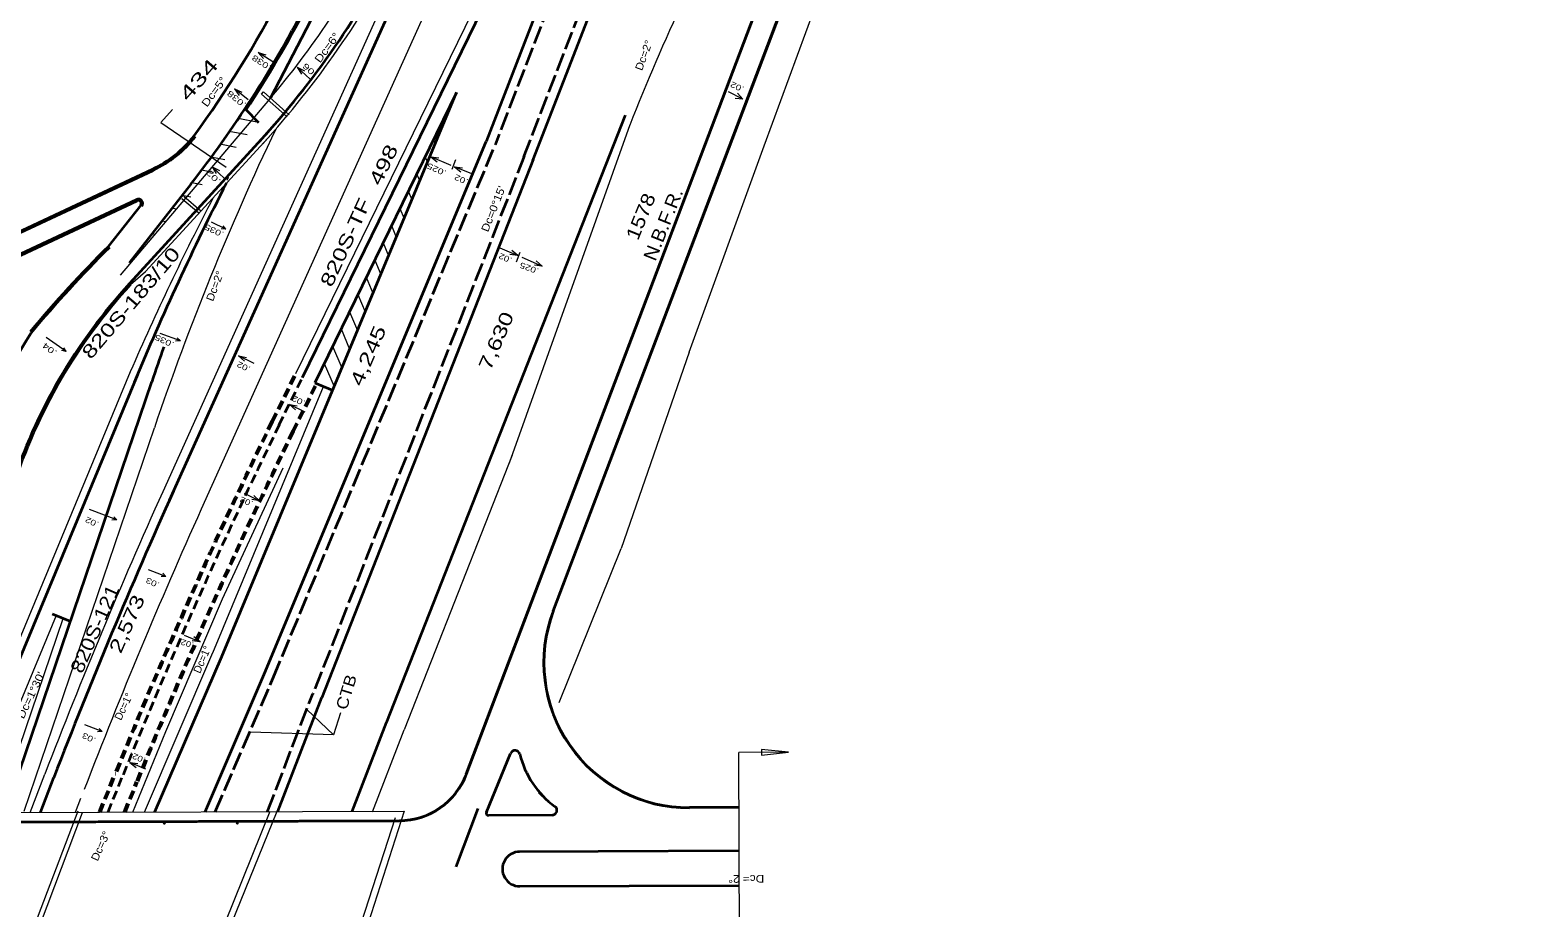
# Model space of a CAD drawing. Extents: x 2354993 to 2372084, y 6966390 to 6990057.
# Drawn here: x 2364884 to 2366452, y 6980481 to 6981393 of the extents above; entities that cross this region are included whole.
import ezdxf

# ---------------------------------------------------------------- set-up
doc = ezdxf.new("R2010")
doc.units = 0
doc.header["$LTSCALE"] = 3.2
doc.header["$PDMODE"] = 32
doc.header["$PDSIZE"] = 1.6
doc.linetypes.add('LONG_DASHED', pattern=[7.5, 6, -1.5])
doc.linetypes.add('MEDIUM_DASHED', pattern=[4.5, 3, -1.5])
for name, color, linetype, lineweight in [('1', 7, 'Continuous', 13), ('11', 7, 'Continuous', 13), ('12', 7, 'Continuous', 13), ('13', 7, 'Continuous', 13), ('15', 7, 'Continuous', 13), ('17', 7, 'Continuous', 13), ('19', 7, 'Continuous', 13), ('2', 7, 'Continuous', 35), ('4', 7, 'Continuous', 13), ('5', 7, 'Continuous', 35), ('7', 7, 'Continuous', 13), ('9', 7, 'Continuous', 13)]:
    doc.layers.add(name, color=color, linetype=linetype, lineweight=lineweight)

msp = doc.modelspace()

# ---------------------------------------------------------------- linework, layer by layer
at = {"layer": '1'}
for p, q in [((2365090.897, 6981239.272), (2365087.397, 6981239.272)), ((2365089.147, 6981241.022), (2365089.147, 6981237.522)), ((2365087.853, 6981186.245), (2365072.864, 6981193.81)), ((2365087.853, 6981186.245), (2365082.859, 6981186.653)), ((2365087.853, 6981186.245), (2365084.997, 6981189.742)), ((2364921.894, 6981059.311), (2364901.059, 6981073.892)), ((2365040.609, 6981070.164), (2365019.682, 6981078.089)), ((2365040.609, 6981070.164), (2365037.401, 6981073.341)), ((2364921.894, 6981059.311), (2364917.006, 6981060.413)), ((2364921.894, 6981059.311), (2364919.555, 6981063.172)), ((2365040.609, 6981070.164), (2365035.6, 6981070.044)), ((2364974.461, 6980884.074), (2364946.096, 6980894.816)), ((2364974.461, 6980884.074), (2364971.253, 6980887.251)), ((2364974.461, 6980884.074), (2364969.452, 6980883.954)), ((2365025.65, 6980825.433), (2365007.554, 6980832.286)), ((2365025.65, 6980825.433), (2365020.641, 6980825.313)), ((2365025.65, 6980825.433), (2365022.442, 6980828.61)), ((2364959.397, 6980664.047), (2364941.301, 6980670.9)), ((2364959.397, 6980664.047), (2364956.189, 6980667.224)), ((2364959.397, 6980664.047), (2364954.388, 6980663.927))]:
    msp.add_line(p, q, dxfattribs=at)
at = {"layer": '11'}
for q in [(2365610.405, 6981329.056), (2365619.803, 6981327.948), (2365617.401, 6981322.432)]:
    msp.add_line((2365625.59, 6981321.562), q, dxfattribs=at)
msp.add_lwpolyline([(2365417.107, 6980596.157), (2365413.024, 6980600.471), (2365417.107, 6980596.157)], dxfattribs=at)
at = {"layer": '12'}
for p, q in [((2365125.058, 6981326.907), (2365127.058, 6981329.143)), ((2365125.058, 6981326.907), (2365151.575, 6981303.182)), ((2365127.058, 6981329.143), (2365153.598, 6981305.398)), ((2365059.879, 6981202.904), (2365042.143, 6981217.955)), ((2365061.904, 6981205.119), (2365044.105, 6981220.225)), ((2364889.34, 6980463.063), (2364934.323, 6980581.712)), ((2364895.069, 6980464.071), (2364938.998, 6980579.939)), ((2365133.691, 6980580.838), (2365086.673, 6980464.691)), ((2365140.767, 6980580.861), (2365093.748, 6980464.714)), ((2365263.831, 6980574.448), (2365228.608, 6980465.09)), ((2365273.39, 6980581.292), (2365235.902, 6980464.902))]:
    msp.add_line(p, q, dxfattribs=at)
at = {"layer": '13'}
msp.add_lwpolyline([(2365032.472, 6981310.938), (2365020.251, 6981297.462), (2365088.313, 6981250.891)], dxfattribs=at)
at = {"layer": '15'}
for p in [(2365672.832, 6980642.571), (2365622.178, 6980409.332)]:
    msp.add_line(p, (2365621.422, 6980642.404), dxfattribs=at)
msp.add_lwpolyline([(2365672.832, 6980642.571), (2365644.822, 6980645.48), (2365644.842, 6980639.481)], close=True, dxfattribs=at)
at = {"layer": '19'}
for p, q in [((2365121.444, 6981370.154), (2365126.945, 6981363.93)), ((2365121.444, 6981370.154), (2365129.403, 6981367.761)), ((2365136.609, 6981360.443), (2365121.444, 6981370.154)), ((2365162.209, 6981354.708), (2365166.546, 6981347.624)), ((2365162.209, 6981354.708), (2365169.632, 6981350.969)), ((2365175.457, 6981342.512), (2365162.209, 6981354.708)), ((2365097.007, 6981332.243), (2365101.772, 6981325.439)), ((2365097.007, 6981332.243), (2365104.646, 6981328.969)), ((2365110.982, 6981320.886), (2365097.007, 6981332.243)), ((2365301.151, 6981261.455), (2365307.649, 6981256.281)), ((2365301.151, 6981261.455), (2365309.405, 6981260.48)), ((2365322.242, 6981252.661), (2365301.151, 6981261.455)), ((2365073.768, 6981251.325), (2365077.965, 6981244.157)), ((2365073.768, 6981251.325), (2365081.116, 6981247.442)), ((2365086.775, 6981238.871), (2365073.768, 6981251.325)), ((2365326.815, 6981258.432), (2365322.862, 6981248.333)), ((2365325.805, 6981251.294), (2365332.303, 6981246.12)), ((2365325.805, 6981251.294), (2365334.058, 6981250.319)), ((2365343.62, 6981243.866), (2365325.805, 6981251.294)), ((2365101.134, 6981054.568), (2365107.331, 6981049.037)), ((2365101.134, 6981054.568), (2365109.32, 6981053.131)), ((2365117.339, 6981046.715), (2365101.134, 6981054.568)), ((2365153.99, 6981004.019), (2365160.187, 6980998.488)), ((2365153.99, 6981004.019), (2365162.176, 6981002.582)), ((2365170.195, 6980996.166), (2365153.99, 6981004.019)), ((2365122.978, 6980903.802), (2365114.831, 6980905.444)), ((2365061.108, 6980757.5), (2365052.846, 6980758.396)), ((2364988.033, 6980631.938), (2364996.28, 6980630.907))]:
    msp.add_line(p, q, dxfattribs=at)
for points in [[(2365106.977, 6980912.062), (2365122.978, 6980903.802), (2365116.923, 6980909.487)], [(2365044.423, 6980764.273), (2365061.108, 6980757.5), (2365054.562, 6980762.612)], [(2365004.606, 6980624.894), (2364988.033, 6980631.938), (2364994.495, 6980626.72)]]:
    msp.add_lwpolyline(points, dxfattribs=at)
at = {"layer": '2'}
for p, q in [((2365683.228, 6982117.169), (2365358.55, 6981277.634)), ((2365407.217, 6981257.934), (2365731.885, 6982097.447)), ((2365029.335, 6980904.779), (2365448.587, 6981835.455)), ((2365382.326, 6981472.187), (2365167.295, 6981031.876)), ((2365083.539, 6980742.181), (2365327.767, 6981328.565)), ((2365327.767, 6981328.565), (2365180.29, 6981026.581)), ((2365132.253, 6981287.979), (2364987.673, 6981129.869)), ((2365127.849, 6980723.726), (2365358.55, 6981277.634)), ((2365407.521, 6981258.707), (2365187.636, 6980699.526)), ((2365051.37, 6981233.14), (2364987.232, 6981151.398)), ((2364999.333, 6981211.369), (2364965.597, 6981168.373)), ((2364987.673, 6981129.869), (2364988.78, 6981128.857)), ((2364995.931, 6981035.023), (2364806.866, 6980579.777)), ((2364861.207, 6980586.955), (2365010.841, 6981027.825)), ((2365180.29, 6981026.581), (2365198.806, 6981019.036)), ((2364926.249, 6980778.591), (2364907.779, 6980786.263)), ((2365014.176, 6980580.45), (2365083.539, 6980742.181)), ((2365066.472, 6980580.62), (2365127.849, 6980723.726)), ((2365141.795, 6980580.864), (2365187.636, 6980699.526)), ((2364766.428, 6980569.647), (2365268.294, 6980571.275))]:
    msp.add_line(p, q, dxfattribs=at)
at = {"layer": '2', "linetype": 'LONG_DASHED'}
for p, q in [((2365692.555, 6982113.562), (2365367.877, 6981274.027)), ((2365397.89, 6981261.541), (2365722.558, 6982101.054)), ((2365137.08, 6980719.881), (2365367.781, 6981273.789)), ((2365398.215, 6981262.367), (2365178.33, 6980703.186)), ((2365076.877, 6980580.654), (2365137.08, 6980719.881)), ((2365131.062, 6980580.83), (2365178.308, 6980703.13))]:
    msp.add_line(p, q, dxfattribs=at)
at = {"layer": '2', "lineweight": 13}
for p, q in [((2365372.833, 6981167.08), (2365391.564, 6981159.03)), ((2365391.564, 6981159.03), (2365383.322, 6981160.095)), ((2365391.564, 6981159.03), (2365385.123, 6981164.274)), ((2365390.132, 6981152.333), (2365393.897, 6981162.504)), ((2365395.606, 6981157.245), (2365416.941, 6981148.076)), ((2365416.941, 6981148.076), (2365410.499, 6981153.32)), ((2365416.941, 6981148.076), (2365408.698, 6981149.141)), ((2365199.84, 6980660.583), (2365172.164, 6980687.071)), ((2365206.926, 6980683.485), (2365199.84, 6980660.583)), ((2365199.84, 6980660.583), (2365113.429, 6980663.421))]:
    msp.add_line(p, q, dxfattribs=at)
at = {"layer": '2', "linetype": 'MEDIUM_DASHED'}
for p, q in [((2365143.357, 6980982.86), (2365166.408, 6981030.061)), ((2364965.372, 6980580.292), (2364980.472, 6980617.592))]:
    msp.add_line(p, q, dxfattribs=at)
at = {"layer": '2'}
for centre, radius, start, end in [((2364406.014, 6981928.856), 968.58, 317.77096, 332.59746), ((2364129.385, 6981956.555), 1144.416, 323.97105, 332.59766), ((2364129.386, 6981956.557), 1171.916, 321.88117, 332.59727), ((2364129.386, 6981956.557), 1173.416, 326.58947, 332.59727), ((2367638.31, 6979928.259), 2864.789, 152.87957, 157.44674), ((2364996.973, 6981213.221), 4.5, 321.88153, 115.06276), ((2364996.973, 6981213.221), 3, 321.88153, 115.06276), ((2365859.616, 6980268.609), 1268.414, 134.80816, 140.24643), ((2365859.616, 6980268.609), 1266.914, 134.80816, 140.24643), ((2365412.01, 6980741.844), 575, 137.55934, 162.17959), ((2365412.01, 6980741.844), 573.5, 137.55934, 162.17959), ((2365412.01, 6980741.844), 625, 147.37736, 162.17959), ((2367728.605, 6980105.384), 2870.041, 160.48763, 161.25221)]:
    msp.add_arc(centre, radius, start, end, dxfattribs=at)
at = {"layer": '2', "linetype": 'MEDIUM_DASHED'}
msp.add_arc((2370304.373, 6978462.422), 5743.578, 153.97093, 157.96139, dxfattribs=at)
at = {"layer": '4'}
for p, q in [((2365645.882, 6982190.639), (2365062.309, 6980895.203)), ((2365290.106, 6981508.007), (2365022.191, 6980913.275)), ((2365364.685, 6981454.295), (2365160.333, 6981035.852)), ((2365133.154, 6981321.567), (2364977.995, 6981138.719)), ((2365135.254, 6981285.334), (2365004.504, 6981142.347)), ((2364988.78, 6981128.857), (2365004.504, 6981142.347)), ((2364988.543, 6981038.091), (2364798.192, 6980579.749)), ((2364878.249, 6980581.158), (2365013.559, 6980979.825)), ((2365136.169, 6980986.37), (2365136.168, 6980986.371)), ((2364911.473, 6980784.729), (2364826.382, 6980579.841)), ((2364853.631, 6980589.527), (2364918.845, 6980781.667)), ((2364884.273, 6980580.029), (2364899.617, 6980619.817)), ((2364973.057, 6980620.594), (2364973.056, 6980620.594)), ((2364931.49, 6980580.182), (2364937.08, 6980594.676))]:
    msp.add_line(p, q, dxfattribs=at)
for centre, radius, start, end in [((2364406.014, 6981928.856), 972.58, 317.77096, 332.59746), ((2364530.202, 6981842.504), 796.823, 319.17372, 334.00023), ((2367722.565, 6980060.369), 2860.789, 154.53387, 161.25242), ((2367561.728, 6979924.188), 2803.937, 152.49424, 156.59276), ((2370277.17, 6978545.992), 5763.578, 155.74921, 158.91113), ((2370277.17, 6978545.992), 5719.578, 155.74921, 158.91113), ((2370277.171, 6978545.993), 5719.578, 155.74921, 158.91113)]:
    msp.add_arc(centre, radius, start, end, dxfattribs=at)
at = {"layer": '5', "lineweight": 13}
for p, q in [((2365337.246, 6980620.046), (2365860.175, 6981999.596)), ((2365429.069, 6980788.933), (2365884.487, 6981990.381)), ((2365121.964, 6981297.375), (2365100.748, 6981301.544)), ((2365507.902, 6981294.902), (2365382.614, 6980943.196)), ((2365110.205, 6981284.399), (2365091.234, 6981288.127)), ((2365303.932, 6981279.375), (2365305.515, 6981275.613)), ((2365086.673, 6981258.449), (2365072.205, 6981261.292)), ((2365098.445, 6981271.423), (2365081.719, 6981274.71)), ((2365295.272, 6981261.277), (2365297.508, 6981255.961)), ((2365074.898, 6981245.476), (2365062.691, 6981247.875)), ((2365063.123, 6981232.503), (2365052.409, 6981234.609)), ((2365286.611, 6981243.18), (2365289.499, 6981236.312)), ((2365051.348, 6981219.53), (2365042.064, 6981221.355)), ((2365277.617, 6981225.874), (2365281.491, 6981216.66)), ((2365036.134, 6981207.233), (2365031.719, 6981208.101)), ((2365268.873, 6981207.97), (2365273.228, 6981197.62)), ((2365025.016, 6981194.131), (2365021.33, 6981194.855)), ((2365260.131, 6981190.069), (2365265.132, 6981178.18)), ((2365002.78, 6981167.927), (2365000.546, 6981168.366)), ((2365013.898, 6981181.029), (2365010.938, 6981181.61)), ((2365251.388, 6981172.166), (2365257.035, 6981158.74)), ((2364991.662, 6981154.825), (2364990.153, 6981155.121)), ((2365242.645, 6981154.264), (2365248.938, 6981139.3)), ((2365233.902, 6981136.361), (2365240.842, 6981119.86)), ((2365225.159, 6981118.458), (2365232.745, 6981100.421)), ((2365216.417, 6981100.556), (2365224.649, 6981080.981)), ((2365207.673, 6981082.652), (2365216.553, 6981061.542)), ((2365198.93, 6981064.75), (2365208.456, 6981042.102)), ((2365569.779, 6981058.596), (2365498.857, 6980854.505)), ((2365190.187, 6981046.847), (2365200.36, 6981022.664)), ((2365074.308, 6980746.026), (2365189.582, 6981022.795)), ((2365385.532, 6980951.387), (2365273.254, 6980665.858)), ((2365084.495, 6980802.006), (2365147.321, 6980938.24)), ((2365434.56, 6980694.195), (2365498.857, 6980854.505)), ((2365025.318, 6980664.238), (2365084.495, 6980802.006)), ((2365003.28, 6980580.415), (2365074.349, 6980746.123)), ((2365240.345, 6980580.67), (2365273.254, 6980665.858)), ((2364991.134, 6980580.375), (2365025.318, 6980664.238)), ((2364766.425, 6980570.647), (2365268.291, 6980572.275)), ((2364776.569, 6980579.679), (2365273.39, 6980581.292)), ((2365621.605, 6980585.953), (2365569.872, 6980585.766))]:
    msp.add_line(p, q, dxfattribs=at)
at = {"layer": '5'}
for p, q in [((2365338.182, 6980619.691), (2365861.11, 6981999.242)), ((2365428.134, 6980789.285), (2365883.552, 6981990.735)), ((2365134.648, 6981323.301), (2365354.45, 6981747.299)), ((2365107.814, 6981311.509), (2365121.964, 6981297.375)), ((2365503.014, 6981304.804), (2365254.641, 6980673.177)), ((2364462.463, 6980991.963), (2365011.662, 6981248.793)), ((2364463.098, 6980990.605), (2365012.297, 6981247.435)), ((2364471.57, 6980972.489), (2364995.066, 6981217.297)), ((2364472.205, 6980971.129), (2364995.702, 6981215.939)), ((2365290.982, 6980765.594), (2365254.641, 6980673.177)), ((2365219.078, 6980581.116), (2365254.798, 6980673.58)), ((2365358.829, 6980580.308), (2365383.947, 6980641.322)), ((2364895.004, 6980580.063), (2364908.948, 6980616.22)), ((2365327.373, 6980523.465), (2365350.309, 6980583.974)), ((2365427.136, 6980577.093), (2365361.15, 6980576.856)), ((2365621.609, 6980584.953), (2365558.252, 6980584.725)), ((2365620.804, 6980540.003), (2365475.062, 6980539.477)), ((2365475.062, 6980539.477), (2365393.369, 6980539.184)), ((2365393.484, 6980503.184), (2365620.901, 6980503.926))]:
    msp.add_line(p, q, dxfattribs=at)
at = {"layer": '5', "linetype": 'MEDIUM_DASHED', "lineweight": 53}
for p, q in [((2365136.168, 6980986.371), (2365160.333, 6981035.852)), ((2365157.922, 6980976.222), (2365182.087, 6981025.703)), ((2364956.731, 6980580.264), (2364973.057, 6980620.594)), ((2364982.689, 6980580.348), (2364995.491, 6980611.973))]:
    msp.add_line(p, q, dxfattribs=at)
at = {"layer": '5', "lineweight": 13}
msp.add_lwpolyline([(2365569.779, 6981058.596), (2365647.705, 6981272.931), (2365768.875, 6981603.207)], dxfattribs=at)
for centre, radius, start, end in [((2368160.706, 6980234.736), 2856.789, 155.3684, 158.22353), ((2365569.331, 6980735.765), 150, 159.24044, 270.20679), ((2365268.051, 6980646.275), 74, 270.18589, 339.24044)]:
    msp.add_arc(centre, radius, start, end, dxfattribs=at)
at = {"layer": '5'}
for centre, radius, start, end in [((2364957.343, 6981360.523), 124.234, 295.92761, 321.67524), ((2364957.108, 6981361.383), 126.61, 295.84286, 321.59049), ((2370277.171, 6978545.993), 5753.578, 155.69737, 158.91113), ((2365569.331, 6980735.765), 151, 159.24044, 270.20679), ((2365388.571, 6980639.418), 5, 14.12521, 157.62419), ((2365487.487, 6980664.31), 97, 194.12521, 233.71172), ((2365268.051, 6980646.275), 75, 270.18589, 339.24044), ((2365361.142, 6980579.356), 2.5, 157.62237, 270.20608), ((2365427.118, 6980582.093), 5, 270.20614, 53.71172), ((2365393.427, 6980521.184), 18, 90.18227, 270.18651)]:
    msp.add_arc(centre, radius, start, end, dxfattribs=at)
at = {"layer": '5', "linetype": 'MEDIUM_DASHED', "lineweight": 53}
for centre, radius in [((2370304.373, 6978462.422), 5751.578), ((2370304.561, 6978462.806), 5727.578)]:
    msp.add_arc(centre, radius, 153.97093, 157.96139, dxfattribs=at)
at = {"layer": '9'}
msp.add_arc((2360722.521, 6984327.136), 5729.573, 359.50797, 359.50797, dxfattribs=at)
for p in [(2365023.897, 6980568.469), (2365099.889, 6980568.715)]:
    msp.add_point(p, dxfattribs=at)

# ---------------------------------------------------------------- texts
at = {"layer": '13'}
for s, height, rotation, width, p in [('434', 14, 49.17, 1.6, (2365048.557, 6981318.421)), ('498', 14, 64.378, 1.4, (2365248.614, 6981230.708)), ('820S-TF', 14, 65.205, 1.35, (2365198.021, 6981125.166)), ('N.B.F.R.', 14, 68.262, 1.1, (2365534.533, 6981152.233)), ('820S-183/10', 14, 49.529, 1.35, (2364947.51, 6981050.143)), ('7,630', 14, 66.706, 1.35, (2365362.921, 6981038.511)), ('4,245', 14, 66.706, 1.4, (2365229.223, 6981021.971)), ('820S-121', 14, 66.256, 1.2, (2364938.424, 6980723.45)), ('2,573', 14, 66.238, 1.35, (2364978.693, 6980744.315)), ('CTB', 12, 72.807, 1.15, (2365213.414, 6980685.71))]:
    msp.add_text(s, height=height, rotation=rotation, dxfattribs=dict(at, width=width)).set_placement(p)
at = {"layer": '17'}
for s, rotation, width, p in [('Dc=6°', 53.429, 1.2, (2365185.862, 6981358.543)), ('Dc=5°', 53.429, 1.2, (2365068.271, 6981312.687)), ("Dc=0°15'", 68.332, 1.15, (2365360.465, 6981182.811)), ('Dc=2°', 69.418, 1.1, (2365074.528, 6981110.713)), ("Dc=1°30'", 64.778, 1.2, (2364877.588, 6980676.573))]:
    msp.add_text(s, height=8, rotation=rotation, dxfattribs=dict(at, width=width)).set_placement(p)
for rotation, p in [(66.444, (2365061.035, 6980723.859)), (64.778, (2364978.891, 6980675.019))]:
    msp.add_text('Dc=1°', height=8, rotation=rotation, dxfattribs=at).set_placement(p)
at = {"layer": '19'}
for s, height, rotation, width, p in [('Dc=2°', 8, 69.681, 1.1, (2365520.616, 6981350.556)), ('.038', 6, 147.408, 1.4, (2365135.804, 6981356.248)), ('.06', 6, 137.408, 1.5, (2365183.353, 6981348.337)), ('.02', 6, 154.917, 1.3, (2365627.397, 6981333.983)), ('.038', 6, 140.942, 1.45, (2365109.71, 6981316.808)), ('.02', 6, 136.287, 1.55, (2365083.184, 6981236.959)), ('.025', 5.999, 155.55, 1.35, (2365317.856, 6981246.809)), ('.02', 6, 155.855, 1.3, (2365340.46, 6981237.835)), ('1578', 14, 67.763, 1.2, (2365516.336, 6981173.829)), ('.035', 5.999, 154.64, 1.35, (2365086.525, 6981183.021)), ('.035', 5.999, 154.83, 1.35, (2365034.729, 6981068.481)), ('.04', 5.999, 143.171, 1.45, (2364912.905, 6981059.251)), ('.02', 6, 154.187, 1.3, (2365114.207, 6981042.942)), ('.02', 6, 154.187, 1.3, (2365171.224, 6981007.688)), ('.02', 6, 157.881, 1.25, (2365116.84, 6980903.297)), ('.02', 5.999, 154.83, 1.3, (2364956.496, 6980881.547)), ('.03', 5.999, 154.83, 1.3, (2365019.593, 6980818.459)), ('.02', 6, 163.09, 1.2, (2365055.041, 6980756.44)), ('.03', 5.999, 154.83, 1.3, (2364953.34, 6980657.073)), ('.02', 6, 157.016, 1.25, (2365005.065, 6980636.453))]:
    msp.add_text(s, height=height, rotation=rotation, dxfattribs=dict(at, width=width)).set_placement(p)
at = {"layer": '2'}
for s, height, rotation, width, p in [('.02', 5.999, 156.311, 1.25, (2365386.068, 6981156.254)), ('.025', 6, 159.683, 1.3, (2365413.904, 6981145.152))]:
    msp.add_text(s, height=height, rotation=rotation, dxfattribs=dict(at, width=width)).set_placement(p)
at = {"layer": '7'}
for s, rotation, width, p in [('Dc=3°', 65.904, 1.1, (2364954.6, 6980528.689)), ('Dc= 2° ', 180.548, 1.15, (2365647.622, 6980515.096))]:
    msp.add_text(s, height=7.999, rotation=rotation, dxfattribs=dict(at, width=width)).set_placement(p)

doc.saveas('drawing.dxf')
